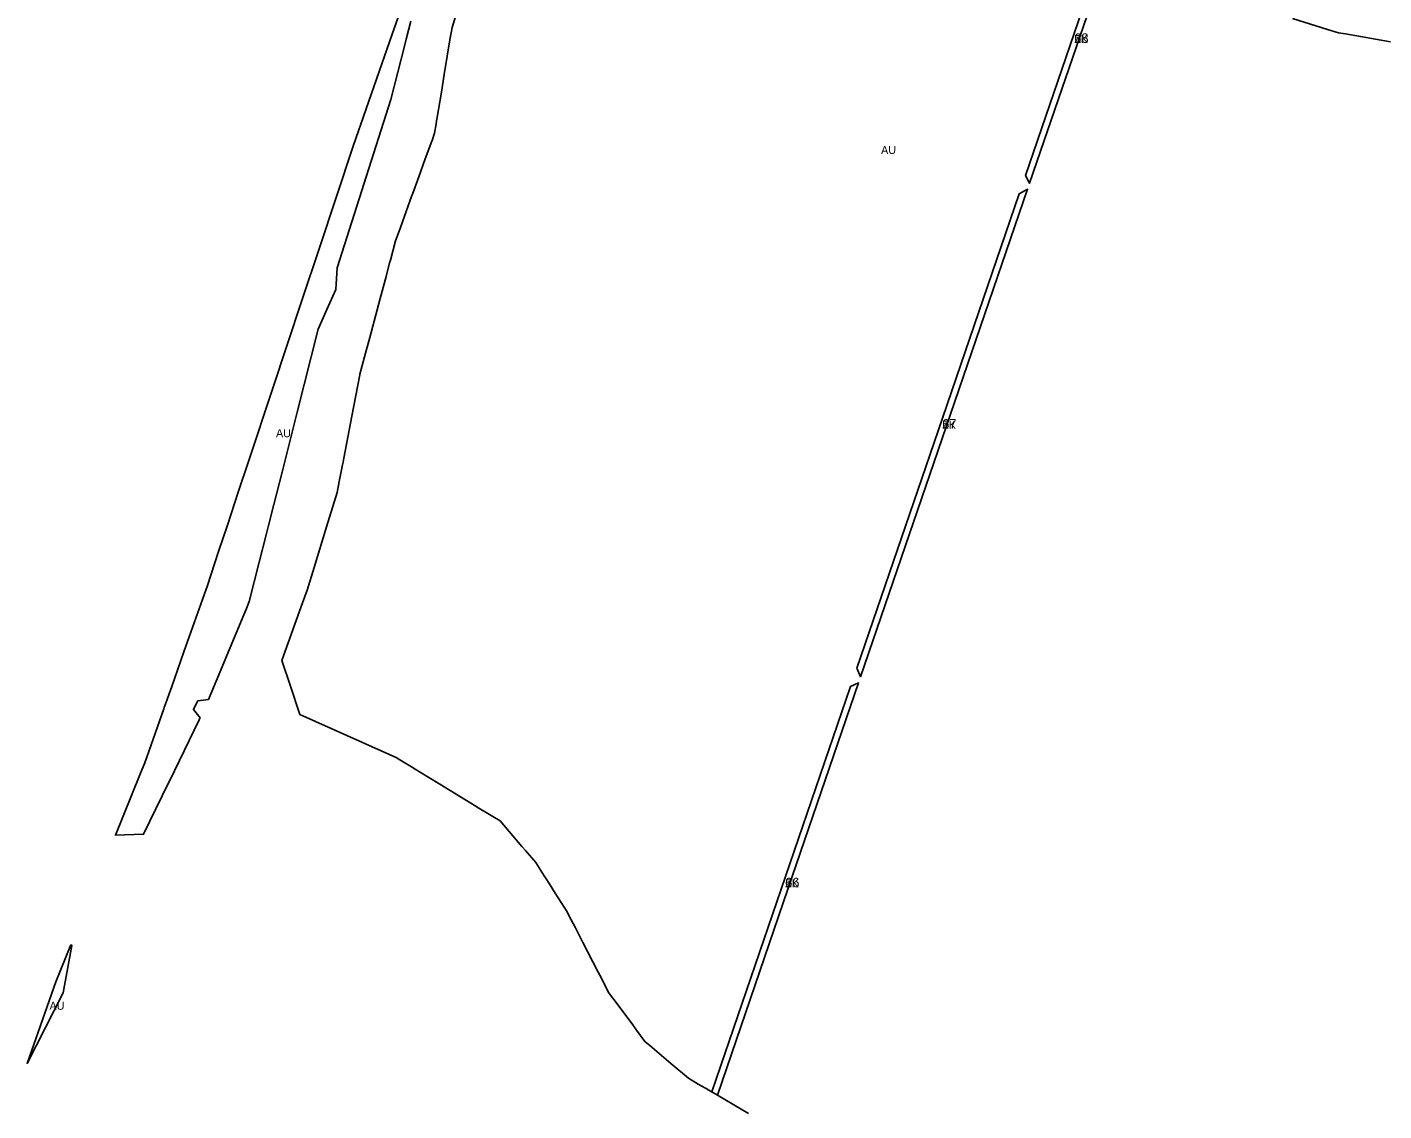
# Model space of a CAD drawing. Extents: x -545779 to -541342, y -1153413 to -1149956.
# Drawn here: x -545687 to -544840, y -1152144 to -1151467 of the extents above; entities that cross this region are included whole.
import ezdxf

# ---------------------------------------------------------------- set-up
doc = ezdxf.new("R2010")
doc.units = 0
for name, color, linetype in [('90710023', 7, 'Continuous'), ('90750013', 7, 'Continuous'), ('ID_navrh', 7, 'Continuous')]:
    doc.layers.add(name, color=color, linetype=linetype)

msp = doc.modelspace()

# ---------------------------------------------------------------- linework, layer by layer
at = {"layer": '90710023'}
for points in [[(-545063.52, -1151560.13), (-545010.42, -1151405.07), (-545006.01, -1151397.05), (-545003.62, -1151393.78), (-545002.59, -1151394.58), (-545060.96, -1151564.98)], [(-545168.93, -1151867.91), (-545118.18, -1151719.72), (-545067.43, -1151571.53), (-545062.25, -1151568.76), (-545113.09, -1151717.19), (-545166.57, -1151873.32)], [(-545216.2, -1152005.93), (-545172.83, -1151879.3), (-545167.86, -1151877.12), (-545211.96, -1152005.88), (-545256.06, -1152134.64), (-545259.58, -1152132.59)]]:
    msp.add_lwpolyline(points, close=True, dxfattribs=at)
at = {"layer": '90750013'}
for points in [[(-545010.42, -1151405.07), (-545063.52, -1151560.13), (-545060.96, -1151564.98), (-545002.59, -1151394.58)], [(-545236.53, -1152146.01), (-545256.06, -1152134.64), (-545211.96, -1152005.88), (-545167.86, -1151877.12), (-545172.83, -1151879.3), (-545216.2, -1152005.93), (-545259.58, -1152132.59), (-545259.63, -1152132.56), (-545263.11, -1152130.53), (-545263.39, -1152130.37), (-545267.99, -1152127.69), (-545274.15, -1152124.11), (-545285.05, -1152114.86), (-545298.3, -1152103.62), (-545301.33, -1152101.06), (-545306.56, -1152093.98), (-545308.94, -1152090.77), (-545318.1, -1152078.38), (-545323.98, -1152070.42), (-545326.14, -1152066.24), (-545329.57, -1152059.61), (-545330.49, -1152057.83), (-545337.17, -1152044.9), (-545340.05, -1152039.33), (-545344.78, -1152030.18), (-545349.03, -1152021.96), (-545349.94, -1152020.19), (-545357.37, -1152008.48), (-545360.76, -1152003.14), (-545366.11, -1151994.69), (-545366.34, -1151994.33), (-545369.55, -1151989.27), (-545376, -1151981.77), (-545378.15, -1151979.27), (-545391.8, -1151963.38), (-545396.43, -1151960.55), (-545406.1, -1151954.65), (-545406.39, -1151954.47), (-545429.39, -1151940.43), (-545436.28, -1151936.22), (-545445.91, -1151930.34), (-545446.03, -1151930.27), (-545455.54, -1151924.46), (-545456.36, -1151923.96), (-545497.27, -1151905.58), (-545516.86, -1151896.78), (-545522.97, -1151878.62), (-545528.2, -1151863.1), (-545515.21, -1151827.17), (-545512.32, -1151819.19), (-545507.95, -1151804.99), (-545500.18, -1151779.69), (-545493.55, -1151758.12), (-545492.25, -1151751.33), (-545490.23, -1151740.79), (-545489.91, -1151739.15), (-545489.46, -1151736.78), (-545484.43, -1151710.54), (-545479.48, -1151684.74), (-545479.34, -1151684.22), (-545475.85, -1151671.11), (-545473.22, -1151661.24), (-545466.73, -1151636.88), (-545463.08, -1151623.18), (-545460.83, -1151614.73), (-545460.35, -1151612.94), (-545457.17, -1151600.98), (-545454.33, -1151593.19), (-545452.86, -1151589.14), (-545446.88, -1151572.71), (-545446.56, -1151571.82), (-545442.62, -1151560.97), (-545438.56, -1151549.82), (-545434.51, -1151538.69), (-545434.33, -1151538.18), (-545432.72, -1151533.76), (-545431.75, -1151527.89), (-545431.45, -1151526.07), (-545431.27, -1151525), (-545428.5, -1151508.15), (-545426.68, -1151497.08), (-545422.89, -1151474.04), (-545422.24, -1151470.08), (-545421.84, -1151467.66), (-545405.63, -1151414.68)], [(-545447.54, -1151463.8), (-545450.39, -1151475.03), (-545451.29, -1151478.56), (-545459.97, -1151512.72), (-545493.67, -1151617.78), (-545494.5, -1151631.31), (-545500.02, -1151643.85), (-545505.41, -1151656.08), (-545518.57, -1151708.09), (-545528.01, -1151745.41), (-545533.15, -1151765.74), (-545536.66, -1151779.63), (-545537.91, -1151784.55), (-545542.27, -1151801.76), (-545548.49, -1151826.34), (-545550.3, -1151830.67), (-545551.92, -1151834.55), (-545562.53, -1151859.93), (-545564.5, -1151864.65), (-545574.05, -1151887.51), (-545580.73, -1151888.36), (-545582.68, -1151892.31), (-545583.36, -1151893.68), (-545579.24, -1151898.96), (-545579.3, -1151899.09), (-545579.79, -1151900.09), (-545598.41, -1151938.49), (-545598.95, -1151939.59), (-545614.52, -1151971.7), (-545632.16, -1151972.33), (-545616.87, -1151934.6), (-545616.4, -1151933.43), (-545613.81, -1151927.06), (-545601.94, -1151893.42), (-545601.58, -1151892.4), (-545599.88, -1151887.59), (-545598.63, -1151884.05), (-545596.99, -1151879.41), (-545589.34, -1151857.74), (-545587.06, -1151851.28), (-545578.84, -1151828), (-545576.52, -1151821.42), (-545574.91, -1151816.87), (-545567.7, -1151795.13), (-545562.17, -1151778.48), (-545559.84, -1151771.45), (-545555.34, -1151757.91), (-545548.76, -1151738.09), (-545534.01, -1151693.64), (-545515.65, -1151638.33), (-545504.73, -1151605.43), (-545483.62, -1151541.82), (-545459.21, -1151471.92), (-545445.56, -1151432.84)], [(-544896.71, -1151462.08), (-544874.81, -1151468.85), (-544867.93, -1151470.97), (-544863.56, -1151471.74), (-544835.58, -1151476.61)]]:
    msp.add_lwpolyline(points, dxfattribs=at)
for points in [[(-545168.93, -1151867.91), (-545166.57, -1151873.32), (-545113.09, -1151717.19), (-545062.25, -1151568.76), (-545067.43, -1151571.53), (-545118.18, -1151719.72)], [(-545664.75, -1152070.69), (-545687.29, -1152114.84), (-545669.26, -1152063.85), (-545659.91, -1152040.78), (-545659.27, -1152041.07)]]:
    msp.add_lwpolyline(points, close=True, dxfattribs=at)

# ---------------------------------------------------------------- texts
at = {"layer": '90710023'}
for p in [(-545033.055, -1151477.342), (-545115.59, -1151718.323), (-545213.72, -1152004.854)]:
    msp.add_text('ZK', height=5, rotation=0, dxfattribs=at).set_placement(p)
at = {"layer": '90750013'}
for rotation, p in [(360, (-545153.741, -1151546.695)), (0, (-545531.785, -1151723.639)), (0, (-545673.28, -1152081.308))]:
    msp.add_text('AU', height=5, rotation=rotation, dxfattribs=at).set_placement(p)
at = {"layer": 'ID_navrh'}
for s, rotation, p in [('68', 0, (-545033.055, -1151477.342)), ('67', 0, (-545115.59, -1151718.323)), ('66', 360, (-545213.72, -1152004.854))]:
    msp.add_text(s, height=6, rotation=rotation, dxfattribs=at).set_placement(p)

doc.saveas('drawing.dxf')
